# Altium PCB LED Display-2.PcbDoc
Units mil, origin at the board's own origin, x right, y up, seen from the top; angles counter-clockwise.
Board outline 2440 x 1500 mil, 2 copper layers (Top Layer, Bottom Layer); 21 components, 47 nets, 153 pads, 42 vias.
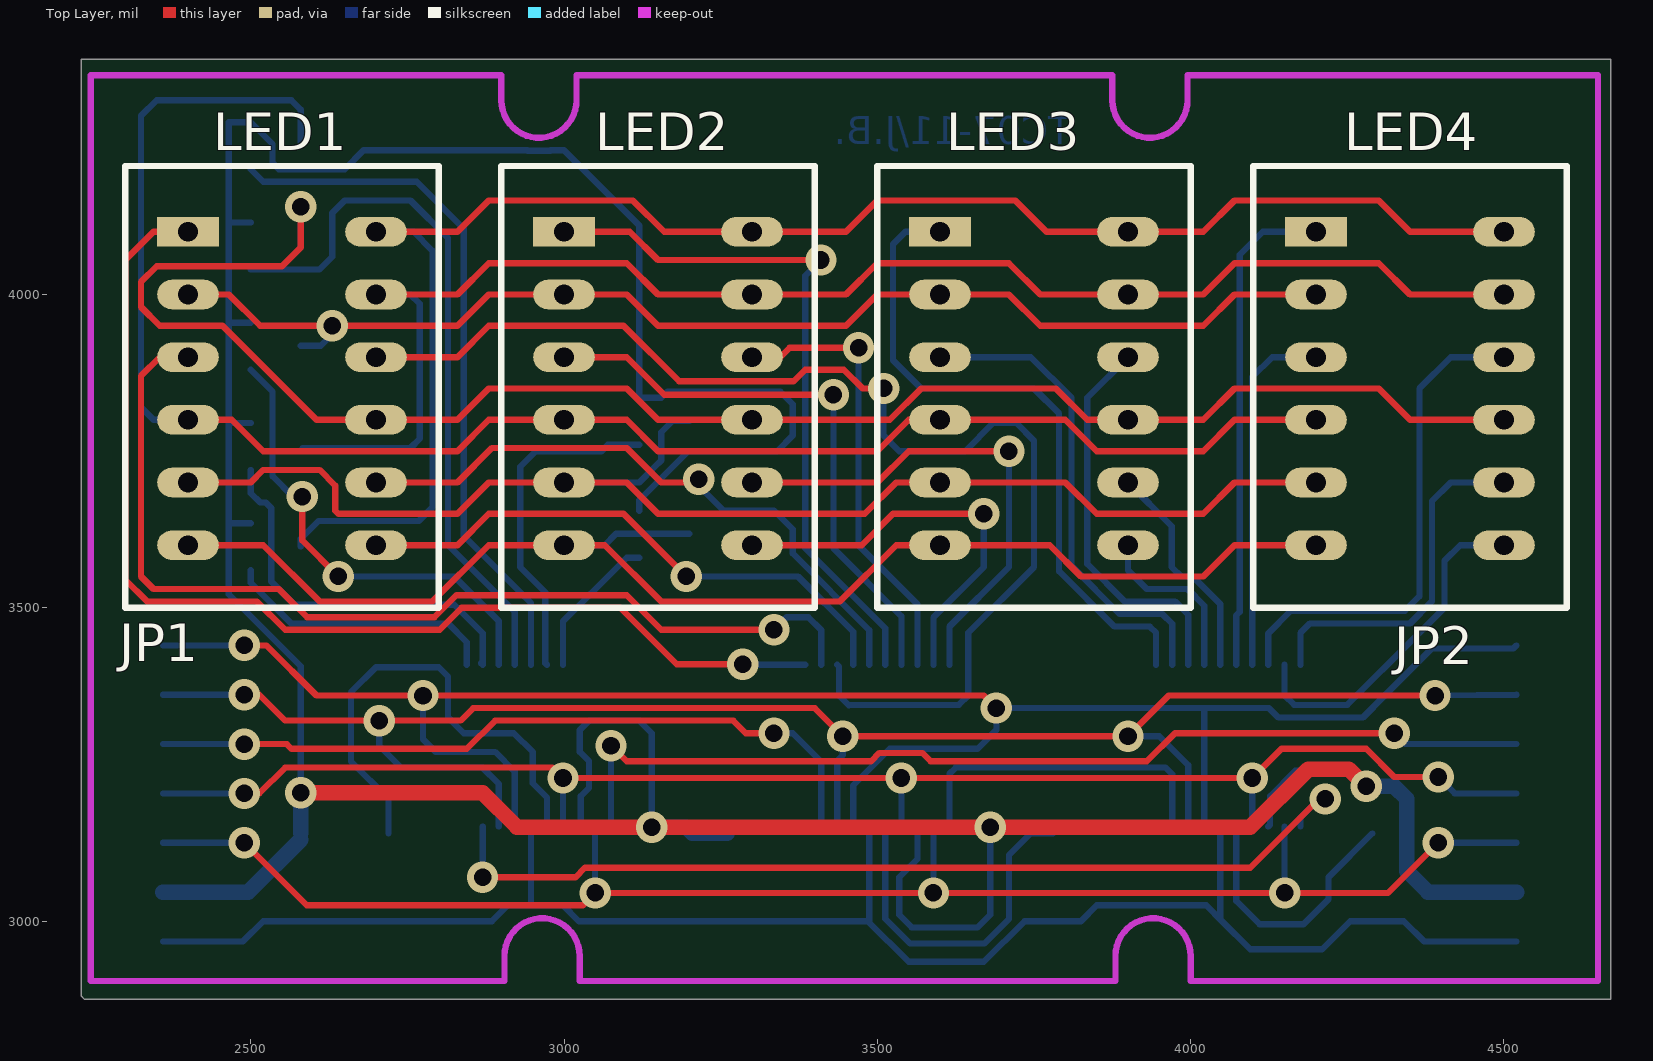
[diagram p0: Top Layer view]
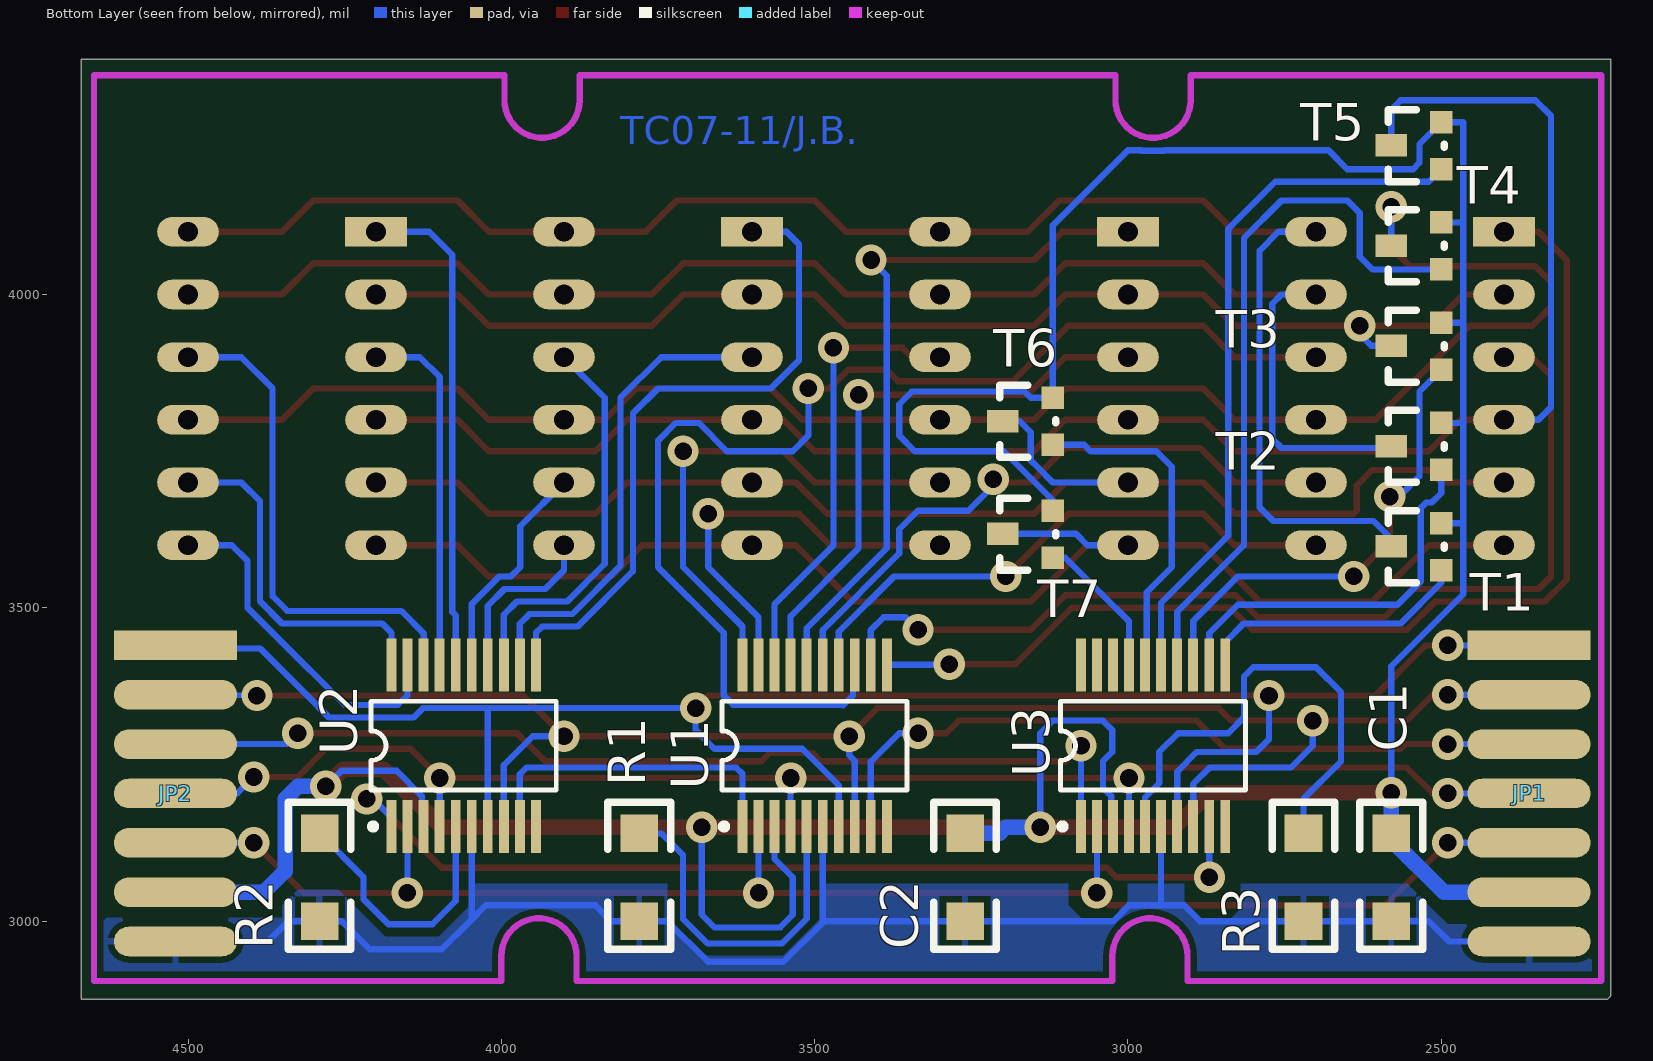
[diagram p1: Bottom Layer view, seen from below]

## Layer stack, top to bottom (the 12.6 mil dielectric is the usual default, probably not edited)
Top Layer: signal copper 1.4
Dielectric: dielectric 12.6, FR-4, Dk 4.8
Bottom Layer: signal copper 1.4

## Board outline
2230,4375 4670,4375 4670,2875 2235,2875 2230,2880 2230,4375

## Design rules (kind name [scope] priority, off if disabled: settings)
Clearance [All] p1: gap=10
PolygonConnect [All] p1: connectstyle=Relief reliefconductorwidth=10 reliefentries=4 polygonreliefangle="90 Angle"
RoutingVias [All] p1: holewidth=28 width=50 viastyle="Through Hole" minholewidth=28 minwidth=50 maxholewidth=28 maxwidth=50
SilkscreenOverComponentPads [All] p1: minsilkscreentomaskgap=10
SolderMaskExpansion [All] p1: expansion=4
Width [All] p1: maxlimit=50 minlimit=10 preferedwidth=10
27 further rules are at their usual default settings.

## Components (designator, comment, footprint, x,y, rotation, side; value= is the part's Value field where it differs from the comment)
C1 "Cap" 1206 2580,3140 r270 bottom
C2 "Cap" 1206 3260,3140 r270 bottom
JP1 "Header 7" ZLACZE-K7 2360,3440 r270 top
JP2 "Header 7" ZLACZE-K7 4520,3440 r270 top
LED1 "TC07-11GWA" TC07-11 2400,4100 r0 top
LED2 "TC07-11GWA" TC07-11 3000,4100 r0 top
LED3 "TC07-11GWA" TC07-11 3600,4100 r0 top
LED4 "TC07-11GWA" TC07-11 4200,4100 r0 top
R1 "Res2" 1206 3780,3140 r270 bottom
R2 "Res2" 1206 4290,3140 r270 bottom
R3 "Res2" 1206 2720,3140 r270 bottom
T1 "BC858B" SOT-23 2500,3560 r90 bottom
T2 "BC858B" SOT-23 2500,3720 r90 bottom
T3 "BC858B" SOT-23 2500,3880 r90 bottom
T4 "BC858B" SOT-23 2500,4040 r90 bottom
T5 "BC858B" SOT-23 2500,4200 r90 bottom
T6 "BC858B" SOT-23 3120,3760 r90 bottom
T7 "BC858B" SOT-23 3120,3580 r90 bottom
U1 "PR4010" SSOP20 3500,3280 r180 bottom
U2 "PR4010" SSOP20 4060,3280 r180 bottom
U3 "PR4010" SSOP20 2960,3280 r180 bottom

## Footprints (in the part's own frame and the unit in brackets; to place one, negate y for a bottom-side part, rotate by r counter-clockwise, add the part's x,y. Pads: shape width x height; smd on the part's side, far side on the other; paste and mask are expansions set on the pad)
1206 [mil]
  rect 60x60 smd: 1(0,0) 2(140,0)
  silkscreen extent -50,-50 185,50
SOT-23 [mil]
  rect 36x36 smd: 1(0,0) 2(75,0)
  rect 36x50 smd: 3(38,80)
  silkscreen extent -20,-5 95,85
SSOP20 [mm] "SSOP, Plastic; 20 Leads; Body Width 5.3 mm; Pitch 0.65 mm"
  rect 0.4x2.15 smd: 1(-2.925,-3.275) 2(-2.275,-3.275) 3(-1.625,-3.275) 4(-0.975,-3.275) 5(-0.325,-3.275) 6(0.325,-3.275) 7(0.975,-3.275) 8(1.625,-3.275) 9(2.275,-3.275) 10(2.925,-3.275) 11(2.925,3.275) 12(2.275,3.275) 13(1.625,3.275) 14(0.975,3.275) 15(0.325,3.275) 16(-0.325,3.275) 17(-0.975,3.275) 18(-1.625,3.275) 19(-2.275,3.275) 20(-2.925,3.275)
  silkscreen extent -3.8,-3.4 3.75,1.8
TC07-11 [mm]
  rect 2.5x1.2 hole 0.8: 1(0,0)
  oval 2.5x1.2 hole 0.8: 2(0,-2.54) 3(0,-5.08) 4(0,-7.62) 5(0,-10.16) 6(0,-12.7) 7(7.62,-12.7) 8(7.62,-10.16) 9(7.62,-7.62) 10(7.62,-5.08) 11(7.62,-2.54) 12(7.62,0)
  silkscreen extent -2.54,-15.24 10.16,2.67
ZLACZE-K7 [mm]
  rect 1.2x5 smd far side: 1(0,0)
  oval 1.2x5 smd far side: 2(2,0) 3(4,0) 4(6,0) 5(8,0) 6(10,0) 7(12,0)

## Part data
C1 C2: "Capacitor"
JP1 JP2: "Header, 7-Pin"
R1 R2 R3: "Resistor"
T1 T2 T3 T4 T5 T6 T7: library part PNP, "PNP Bipolar Transistor"

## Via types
v1: diameter 50, hole 28, Top Layer to Bottom Layer, 42 vias

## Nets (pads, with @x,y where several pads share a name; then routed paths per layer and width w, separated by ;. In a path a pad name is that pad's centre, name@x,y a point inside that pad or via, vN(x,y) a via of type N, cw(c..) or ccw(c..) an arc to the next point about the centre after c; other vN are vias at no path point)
C1-1: LED1.1 U1.11 | length 1798.8
  Top Layer w10: LED1.1 2345,4100 2300,4055 2300,3545 2335,3510 2443.43,3510 2510,3510 2555,3465 2801.57,3465 2836.57,3500 3090,3500 3180,3410 v1(3285,3410)
  Bottom Layer w10: v1(3285,3410) 3286.06,3408.94 U1.11
C1-2: LED1.3 U1.12 | length 1629.4
  Top Layer w10: LED1.3 2355,3900 2325,3870 2325,3550 2345,3530 2495.15,3530 2545,3530 2590,3485 2793.28,3485 2828.28,3520 3100,3520 3155,3465 v1(3335,3465)
  Bottom Layer w10: v1(3335,3465) 3355,3485 3390,3485 3410.43,3464.57 U1.12
C1-3: LED1.10 U1.13 | length 1965.8
  Top Layer w10: LED1.10 2830,3900 2880,3950 3095,3950 3183.62,3861.38 3366.38,3861.38 3385,3880 3446.57,3880 3476.57,3850 3500,3850 v1@3510,3860
  Bottom Layer w10: U1.13 3438.74,3406.22 3438.74,3360.4 3454.57,3344.57 ; 3455,3345 3630,3345 3645,3360 3645,3460 3750,3565 3750,3766.57 3721.57,3795 3685,3795 3640,3750 3535,3750 3510,3775 v1(3510,3850)
C1-4: LED1.7 U1.14 | length 913.2
  Top Layer w10: LED1.7 2830,3600 2880,3650 3095,3650 v1(3195,3550)
  Bottom Layer w10: v1(3195,3550) 3373.43,3550 3461.61,3461.82 U1.14
C1-5: LED1.8 U1.15 | length 1018.4
  Top Layer w10: LED1.8 2830,3700 2885,3755 3100,3755 3155,3700 3210,3700 v1(3215,3705)
  Bottom Layer w10: v1(3215,3705) 3215,3695 3255,3655 3335.21,3655 3365,3625.21 3365,3586.72 3487.2,3464.51 U1.15
C2-1: LED2.1 U1.16 | length 1138
  Top Layer w10: LED2.1 3105,4100 3150,4055 v1(3410,4055)
  Bottom Layer w10: v1(3410,4055) 3385,4030 3385,3595 3512.8,3467.2 U1.16
C2-2: LED2.3 U1.17 | length 930.8
  Top Layer w10: LED2.3 3100,3900 3160,3840 v1(3430,3840)
  Bottom Layer w10: v1(3430,3840) 3430,3595 3538.39,3486.61 U1.17
C2-3: LED2.10 U1.18 | length 727.4
  Top Layer w10: LED2.10 3345,3900 3360,3915 v1(3470,3915)
  Bottom Layer w10: v1@3455,3915 3470,3900 3470,3823.43 3470,3600 3563.98,3506.02 U1.18
C2-4: LED2.7 U1.19 | length 665.1
  Top Layer w10: LED2.7 3475,3600 3525,3650 v1(3670,3650)
  Bottom Layer w10: U1.19 3589.57,3484.57 3670,3565 3670,3620 v1(3670,3650)
C2-5: LED2.8 U1.20 | length 811.1
  Top Layer w10: LED2.8 3500,3700 3550,3750 v1(3710,3750)
  Bottom Layer w10: U1.20 3615.16,3470.16 3710,3565 3710,3650 v1(3710,3750)
C3-1: LED3.1 U2.11 | length 1067
  Bottom Layer w10: LED3.1 3545,4100 3525,4080 3525,3894.79 3569.79,3850 3750,3850 3790,3810 3790,3558.43 3878.43,3470 3935,3470 3944.84,3460.16 U2.11
C3-2: LED3.3 U2.12 | length 769.4
  Bottom Layer w10: LED3.3 3745,3900 3810,3835 3810,3566.72 3886.72,3490 3955,3490 3970.43,3474.57 U2.12
C3-3: LED3.10 U2.13 | length 631.5
  Bottom Layer w10: LED3.10 3835,3835 3835,3570 3895,3510 3975,3510 3996.02,3488.98 U2.13
C3-4: LED3.7 U2.14 | length 279.5
  Bottom Layer w10: LED3.7 3900,3560 3930,3530 3995,3530 4021.61,3503.39 U2.14
C3-5: LED3.8 U2.15 | length 362.7
  Bottom Layer w10: LED3.8 3970,3630 3970,3565 3985,3550 4003.28,3550 4047.2,3506.08 U2.15
C4-1: LED4.1 U2.16 | length 793.5
  Bottom Layer w10: U2.16 4072.8,3487.8 4078.39,3493.39 4078.39,4063.39 4115,4100 LED4.1
C4-2: LED4.3 U2.17 | length 574.2
  Bottom Layer w10: U2.17 4098.39,3868.39 4130,3900 LED4.3
C4-3: LED4.10 U2.18 | length 803.1
  Bottom Layer w10: U2.18 4123.98,3458.98 4160,3495 4341.72,3495 4365,3518.28 4365,3850 4415,3900 LED4.10
C4-4: LED4.7 U2.19 | length 554.9
  Bottom Layer w10: U2.19 4149.57,3360.43 4165,3345 4250,3345 4360,3455 4405,3500 4405,3575 4430,3600 LED4.7
C4-5: LED4.8 U2.20 | length 568.9
  Bottom Layer w10: U2.20 4175.16,3459.84 4190.32,3475 4350,3475 4385,3510 4385,3670 4415,3700 LED4.8
GND: C1.2 C2.2 JP1.7 JP2.7 R1.2 R2.2 R3.2 U1.6 U2.6 U3.6 | length 2743.4
  Bottom Layer w10: JP1.7 2487.56,2967.56 2520,3000 2560,3000 2700,3000 2885,3000 2910.33,3025.33 2998.42,3025.33 3023.75,3000 3240,3000 3485,3000 3550,2935 3670,2935 3735,3000 R1.2 3825,3000 3850.33,3025.33 4024.67,3025.33 4050,3000 4095,2955 4209.69,2955 4254.69,3000 4340,3000 4372.44,2967.56 JP2.7 ; 2947.2,3027.53 U3.6 ; 3487.2,3000 U1.6 ; 4047.2,3002.2 U2.6
NetJP1_1: JP1.1 JP2.1 U1.7 U2.7 U3.7 | length 3137.3
  Top Layer w10: v1(2490,3440) 2525,3440 2605,3360 v1(2775,3360) 2805,3360 3670,3360 v1(3690,3340)
  Bottom Layer w10: JP1.1 v1(2490,3440) ; v1(2775,3360) 2775,3290 2795,3270 2890,3270 2921.61,3238.39 U3.7 ; U1.7 3461.61,3216.61 3520,3275 3660,3275 3690,3305 v1(3690,3340) 4125,3340 4140,3325 4275,3325 4310,3360 4385,3435 4515,3435 JP2.1 ; U2.7@4018.9,3153.78 U2.7 4021.61,3338.39
NetJP1_2: JP1.2 JP2.2 U1.8 U2.8 U3.8 | length 2925.8
  Top Layer w10: v1(2490,3361.26) 2513.74,3361.26 2555,3320 2680,3320 2740,3320 2835,3320 2855,3340 3400,3340 v1(3445,3295) v1(3900,3295) 3965,3360 v1(4390,3360) v1@4400,3360
  Bottom Layer w10: JP1.2 v1(2490,3361.26) ; v1(2705,3320) 2705,3295 2705,3280 2740,3245 2870,3245 2896.02,3218.98 U3.8 ; U1.8 3436.02,3256.02 3445,3265 v1(3445,3295) ; v1(3900,3295) 3950,3295 3996.02,3248.98 U2.8 ; v1(4390,3360) JP2.2
NetJP1_3: JP1.3 U1.9 | length 1202.8
  Top Layer w10: v1(2490,3282.52) 2557.48,3282.52 2565,3275 2845,3275 2890,3320 3270,3320 3290,3300 v1(3335,3300)
  Bottom Layer w10: JP1.3 v1(2490,3282.52) ; v1(3335,3300) 3365,3300 3410.43,3254.57 U1.9
NetJP1_4: JP1.4 JP2.4 U1.4 U2.4 U3.4 | length 2462.4
  Top Layer w10: v1(2490,3203.78) 2513.78,3203.78 2555,3245 2981.77,3245 v1(2998.39,3228.39) v1(3538.39,3228.39) v1(4098.39,3228.39) ; v1@4100,3230 4145,3275 4280,3275 4325,3230 v1(4395,3230)
  Bottom Layer w10: JP1.4 v1(2490,3203.78) ; U3.4 v1(2998.39,3228.39) ; U1.4 v1(3538.39,3228.39) ; U2.4 v1(4098.39,3228.39) ; v1(4395,3230) 4421.22,3203.78 JP2.4
NetJP1_5: JP1.5 JP2.5 U1.2 U2.2 U3.2 | length 2561
  Top Layer w10: v1(2489.96,3125.04) 2589.67,3025.33 2605.33,3025.33 3030.33,3025.33 v1(3050,3045) v1(3589.57,3045) v1(4150,3045) 4315,3045 v1(4395.04,3125.04)
  Bottom Layer w10: JP1.5 JP1.5 v1(2489.96,3125.04) ; U3.2 3049.57,3045.43 v1(3050,3045) ; v1(3589.57,3045) U1.2 ; v1@4149.57,3045 U2.2 ; v1(4395.04,3125.04) JP2.5
NetJP2_3: JP2.3 U3.1 | length 1621.1
  Top Layer w10: v1(3075,3280) 3100,3255 3490,3255 3503.39,3268.39 3571.61,3268.39 3585,3255 3930,3255 3975,3300 v1(4325,3300)
  Bottom Layer w10: U3.1 v1@3075.16,3279.84 ; v1(4325,3300) 4342.48,3282.52 JP2.3
NetR1_1: R1.1 U1.5 | length 563.3
  Bottom Layer w10: U1.5 3512.8,3003.92 3552.57,2964.14 3670.86,2964.14 3710,3003.28 3710,3105 3745,3140 R1.1
NetR2_1: R2.1 U2.5 | length 432
  Bottom Layer w10: U2.5 4072.8,3032.2 4110,2995 4180,2995 4220,3035 4220,3070 R2.1
NetR3_1: R3.1 U3.5 | length 778.8
  Bottom Layer w10: R3.1 2720,3195 2660,3255 2660,3365 2700,3405 2800,3405 2815,3390 2815,3325 2840,3300 2920,3300 2950,3270 2950,3220.2 2972.8,3197.41 U3.5
NetU1_1: U1.1 U2.9 | length 531.3
  Bottom Layer w10: U1.1 3615.16,3235.16 3625,3245 3960,3245 3970.43,3234.57 U2.9
NetU2_1: U2.1 U3.9 | length 1539.1
  Top Layer w10: v1(2870,3070) 3018.43,3070 3033.43,3085 4095,3085 4205,3195 v1(4215,3195)
  Bottom Layer w10: v1@2870.43,3075 U3.9 ; U2.1 4175.16,3165.16 4205,3195 v1(4215,3195)
QR1: LED1.12 LED2.12 LED3.12 LED4.12 T1.3 | length 2679.4
  Top Layer w10: LED1.12 2830,4100 2880,4150 3110,4150 3160,4100 LED2.12 3450,4100 3500,4150 3720,4150 3770,4100 LED3.12 4020,4100 4070,4150 4300,4150 4350,4100 LED4.12
  Bottom Layer w10: T1.3 2580,3610 2608.62,3638.62 2768.62,3638.62 2790,3660 2790,4070 2760,4100 LED1.12
QR2: LED1.11 LED2.11 LED3.11 LED4.11 T2.3 | length 2408.7
  Top Layer w10: LED1.11 2830,4000 2880,4050 3100,4050 3150,4000 LED2.11 3450,4000 3500,4050 3710,4050 3760,4000 LED3.11 4020,4000 4070,4050 4300,4050 4350,4000 LED4.11
  Bottom Layer w10: T2.3@2583,3755 2755,3755 2770,3770 2770,3985 2755,4000 LED1.11
QR3: LED1.2 LED2.2 LED3.2 LED4.2 T3.3 | length 1995.7
  Top Layer w10: LED1.2 2465,4000 2515,3950 v1(2630,3950) 2830,3950 2880,4000 LED2.2 3100,4000 3150,3950 3450,3950 3500,4000 LED3.2 3710,4000 3760,3950 4020,3950 4070,4000 LED4.2
  Bottom Layer w10: T3.3 2612,3918 2630,3936 v1(2630,3950)
QR4: LED1.9 LED2.9 LED3.9 LED4.9 T4.3 | length 2818.6
  Top Layer w10: v1(2580,4140) 2580,4075 2550,4045 2350,4045 2325,4020 2325,3980 2355,3950 2455,3950 2605,3800 LED1.9 2830,3800 2880,3850 3100,3850 3150,3800 LED2.9 3519.79,3800 3569.79,3850 3785,3850 3835,3800 LED3.9 4020,3800 4070,3850 4300,3850 4350,3800 LED4.9
  Bottom Layer w10: T4.3 v1(2580,4140)
QR5: LED1.4 LED2.4 LED3.4 LED4.4 T5.3 | length 2801.1
  Top Layer w10: LED1.4 2470,3800 2520,3750 2830,3750 2880,3800 LED2.4 3100,3800 3150,3750 3500,3750 3550,3800 LED3.4 3800,3800 3850,3750 4020,3750 4070,3800 LED4.4
  Bottom Layer w10: LED1.4 2345,3800 2325,3820 2325,4285 2350,4310 2565,4310 2580,4295 T5.3
QR6: LED1.5 LED2.5 LED3.5 LED4.5 T6.3 | length 2231.2
  Top Layer w10: LED1.5 2500,3700 2520,3720 2610,3720 2635,3695 2635,3655 2640,3650 2830,3650 2880,3700 LED2.5 3100,3700 3150,3650 3480,3650 3530,3700 LED3.5 3800,3700 3850,3650 4020,3650 4070,3700 LED4.5
  Bottom Layer w10: LED2.5 3120,3700 3145,3725 3155,3735 3155,3780 3173,3798 T6.3
QR7: LED1.6 LED2.6 LED3.6 LED4.6 T7.3 | length 2198
  Top Layer w10: LED1.6 2520,3600 2610,3510 2790,3510 2880,3600 LED2.6 3065,3600 3155,3510 3440,3510 3530,3600 LED3.6 3775,3600 3825,3550 4020,3550 4070,3600 LED4.6
  Bottom Layer w10: LED2.6 3065,3600 3083,3618 T7.3
R1: T1.1 U3.11 | length 440.3
  Bottom Layer w10: T1.1 2500,3540 2565,3475 2815,3475 2844.84,3445.16 U3.11
R2: T2.1 U3.12 | length 623.1
  Bottom Layer w10: T2.1 2500,3683 2515,3668 2524.21,3668 2533,3659.21 2533,3542 2570,3505 2825,3505 2870.43,3459.57 U3.12 U3.12@2867.72,3411.66
R3: T3.1 U3.13 | length 752.3
  Top Layer w10: v1(2582.5,3677.5) 2582.5,3607.5 v1(2640,3550)
  Bottom Layer w10: T3.1 2535,3845 2535,3710.01 2567.51,3677.5 v1(2582.5,3677.5) ; v1(2640,3550) 2825,3550 2896.02,3478.98 U3.13
R4: T4.1 U3.14 | length 1151.6
  Bottom Layer w10: T4.1 2610,4040 2630,4060 2630,4130 2650,4150 2755,4150 2815,4090 2815,3600 2921.61,3493.39 U3.14
R5: T5.1 U3.15 | length 1119.8
  Bottom Layer w10: T5.1 2520,4180 2765,4180 2840,4105 2840,3866.57 2840,3615 2947.2,3507.8 U3.15
R6: T6.1 U3.16 | length 538.3
  Bottom Layer w10: U3.16 2970.08,3411.66 2970.08,3524.92 2930,3565 2930,3725 2955,3750 3060,3750 3070,3760 T6.1
R7: T7.1 U3.17 | length 233.2
  Bottom Layer w10: U3.17 2998.39,3478.39 3041.59,3521.59 3100,3580 T7.1
VCC: C1.1 C2.1 JP1.6 JP2.6 T1.2 T2.2 T3.2 T4.2 T5.2 T6.2 T7.2 U1.3 U2.3 U3.3 | length 6645.4
  Top Layer w25: v1(2580,3205) 2870,3205 2925,3150 v1(3140,3150) v1(3680,3150) 4095,3150 4187.5,3242.5 4252.5,3242.5 v1(4280,3215)
  Bottom Layer w10: T1.2 2465,3635 ; T2.2 2465,3795 ; T3.2 2465,3955 ; T4.2 2465,4115 ; C1.1@2580,3130 C1.1 ; v1(2580,3205) 2580,3406.57 2465,3521.57 2465,3635 ; U3.3 3026.69,3153.78 3026.69,3199.6 3040,3212.91 3040,3255 3025,3270 3025,3305 3040,3320 3120,3320 3140,3300 v1(3140,3150) ; T7.2 3120,3671.72 3153.28,3705 3198.28,3750 3340,3750 3365,3775 3365,3825 3345,3845 3165,3845 3155,3835 T6.2 3120,4110 3000,4230 2978.82,4230 2978.13,4229.31 2941.87,4229.31 2941.18,4230 2850,4230 2680,4230 2650,4200 2545,4200 2535,4210 2535,4240 T5.2 2465,4275 2465,4115 ; U1.3 3563.98,3098.98 3535,3070 3535,3010 3555,2990 3660,2990 3680,3010 v1(3680,3150) ; U2.3 4126.69,3153.78 4126.69,3199.6 4167.09,3240 4255,3240 v1(4280,3215) ; 2465,3635 2465,3795 ; 2465,3795 2465,3955 ; 2465,3955 2465,4115
  Bottom Layer w25: JP1.6 2496.3,3046.3 C1.1@2580,3130 ; C1.1 v1(2580,3205) ; v1(3140,3150) 3195,3150 3205,3140 C2.1 ; v1(4280,3215) 4325,3215 4345,3195 4345,3080 4378.7,3046.3 JP2.6
pads on no net: U1.10 U2.10 U3.10 U3.18 U3.19 U3.20

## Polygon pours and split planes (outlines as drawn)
GND on Bottom Layer "GND" (solid, remove dead copper, pour order 1000): 2255,2915 4635,2915 4635,3000 4630,3005 4350,3005 4350,3025 4325,3050 4260,3050 4225,3015 4185,2975 4100,2975 4060,3015 4047.2,3027.8 4047.2,3060 3735,3060 3735,3000 3680,2945 3675,2945 3550,2945 3487.2,3007.8 3487.2,3030 3487.2,3060 3095,3060 3095,3025 3080,3010 3070,3000 3040,3000 3025,3000 3015,3010 3000,3025 3000,3055 3000,3060 2910,3060 2910,3025.65 2910.33,3025.33 2885,3000 2840,3000 2820,3020 2820,3060 2555,3060 2515,3020 2490,2995 2255,2995

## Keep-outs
Keep-Out Layer:
  lines w10: 2245,2905 2245,4350 2900,4350 2900,4310 ccw(c2960,4310) 3020,4310 3020,4350 3875,4350 3875,4310 ccw(c3935,4310) 3995,4310 3995,4350 4650,4350 4650,2905 ; 2245.36,2904.64 2905,2904.64 2905,2944.64 cw(c2965,2944.64) 3025,2944.64 3025,2904.64 3880,2904.64 3880,2944.64 cw(c3940,2944.64) 4000,2944.64 4000,2904.64 4649.64,2904.64

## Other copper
Bottom Layer:
  text "TC07-11/J.B." at 3810,4240 h45

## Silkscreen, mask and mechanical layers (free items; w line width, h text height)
Mechanical 1:
  lines w10: 2245,2905 2245.36,2904.64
